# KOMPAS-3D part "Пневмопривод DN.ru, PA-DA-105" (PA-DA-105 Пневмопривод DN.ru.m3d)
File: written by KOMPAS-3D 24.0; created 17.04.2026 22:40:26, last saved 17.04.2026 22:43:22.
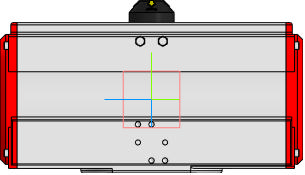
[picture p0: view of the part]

Document properties: Автор: DN.ru; Полное имя файла: C:\Работа\PA-DA-х Пневмопривод DN.ru\105\PA-DA-105 Пневмопривод DN.ru.m3d

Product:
- Part/product: Пневмопривод DN.ru  | designation PA-DA-105
    Масса: 6.8
    Раздел спецификации: Прочие изделия
    Примечание: D290-00296

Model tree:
1. Операция без истории:1

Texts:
  PA-DA-105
